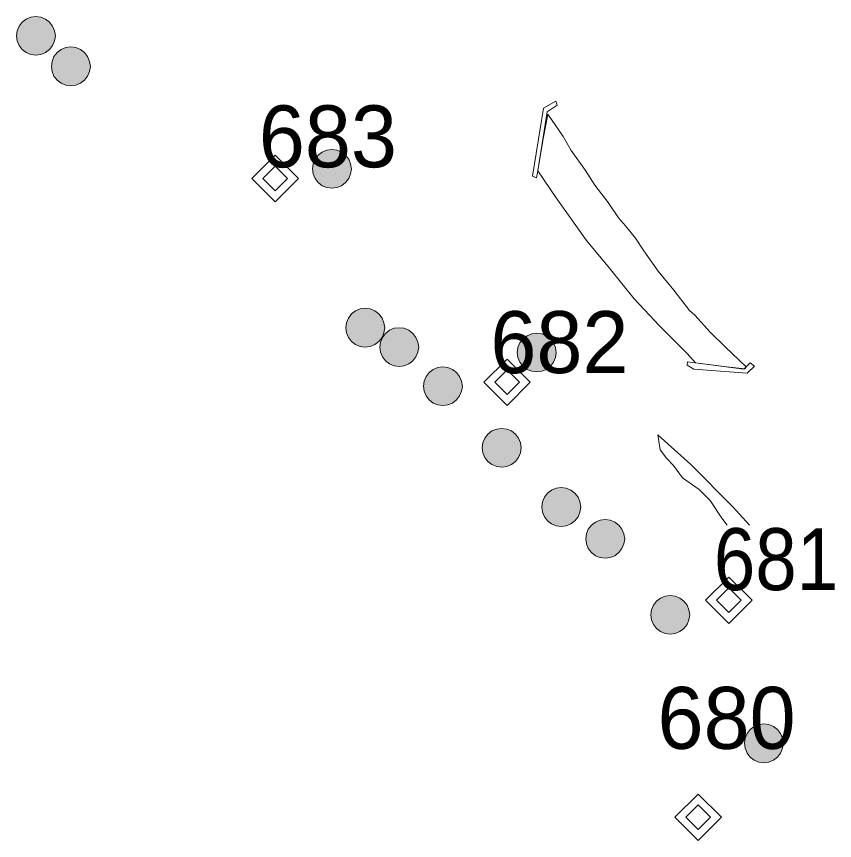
# Model space of a CAD drawing. Extents: x 3461750 to 3585707, y 5917729 to 5985917.
# Drawn here: x 3520979 to 3523622, y 5966054 to 5968716 of the extents above; entities that cross this region are included whole.
import ezdxf

# ---------------------------------------------------------------- set-up
doc = ezdxf.new("R2010")
doc.units = 0
doc.header["$LTSCALE"] = 80
for name, color, linetype, lineweight in [('13', 7, 'Continuous', 13), ('15', 7, 'Continuous', 13), ('2', 7, 'Continuous', 13), ('3', 7, 'Continuous', 13), ('6', 7, 'Continuous', 13), ('7', 7, 'Continuous', 13)]:
    doc.layers.add(name, color=color, linetype=linetype, lineweight=lineweight)

msp = doc.modelspace()

# ---------------------------------------------------------------- hatches: boundary and pattern name
at = {"layer": '3'}
for points in [[(3521105.17, 5968653.09), (3521102.24, 5968669.71), (3521095.99, 5968684.8), (3521086.04, 5968697.76), (3521073.08, 5968707.71), (3521057.99, 5968713.96), (3521041.8, 5968716.09), (3521025.6, 5968713.96), (3521010.51, 5968707.71), (3520997.55, 5968697.76), (3520987.61, 5968684.8), (3520981.35, 5968669.71), (3520979.22, 5968653.52), (3520981.35, 5968637.32), (3520987.61, 5968622.23), (3520997.55, 5968609.27), (3521010.51, 5968599.32), (3521025.6, 5968593.07), (3521041.8, 5968590.94), (3521057.99, 5968593.07), (3521073.08, 5968599.32), (3521086.04, 5968609.27), (3521095.99, 5968622.23), (3521102.24, 5968637.32)], [(3521217.82, 5968554.55), (3521214.89, 5968571.18), (3521208.63, 5968586.27), (3521198.69, 5968599.23), (3521185.73, 5968609.17), (3521170.64, 5968615.42), (3521154.44, 5968617.56), (3521138.25, 5968615.42), (3521123.16, 5968609.17), (3521110.2, 5968599.23), (3521100.25, 5968586.27), (3521094, 5968571.18), (3521091.87, 5968554.98), (3521094, 5968538.78), (3521100.25, 5968523.69), (3521110.2, 5968510.73), (3521123.16, 5968500.79), (3521138.25, 5968494.54), (3521154.44, 5968492.4), (3521170.64, 5968494.54), (3521185.73, 5968500.79), (3521198.69, 5968510.73), (3521208.63, 5968523.69), (3521214.89, 5968538.78)], [(3522061.66, 5968223.2), (3522058.73, 5968239.83), (3522052.48, 5968254.92), (3522042.54, 5968267.88), (3522029.58, 5968277.82), (3522014.49, 5968284.08), (3521998.29, 5968286.21), (3521982.1, 5968284.08), (3521967, 5968277.82), (3521954.04, 5968267.88), (3521944.1, 5968254.92), (3521937.85, 5968239.83), (3521935.72, 5968223.63), (3521937.85, 5968207.44), (3521944.1, 5968192.35), (3521954.04, 5968179.39), (3521967, 5968169.44), (3521982.1, 5968163.19), (3521998.29, 5968161.06), (3522014.49, 5968163.19), (3522029.58, 5968169.44), (3522042.54, 5968179.39), (3522052.48, 5968192.35), (3522058.73, 5968207.44)], [(3522169.23, 5967710.22), (3522166.3, 5967726.84), (3522160.05, 5967741.93), (3522150.11, 5967754.89), (3522137.15, 5967764.84), (3522122.05, 5967771.09), (3522105.86, 5967773.22), (3522089.66, 5967771.09), (3522074.57, 5967764.84), (3522061.61, 5967754.89), (3522051.67, 5967741.93), (3522045.42, 5967726.84), (3522043.28, 5967710.64), (3522045.42, 5967694.45), (3522051.67, 5967679.36), (3522061.61, 5967666.4), (3522074.57, 5967656.45), (3522089.66, 5967650.2), (3522105.86, 5967648.07), (3522122.05, 5967650.2), (3522137.15, 5967656.45), (3522150.11, 5967666.4), (3522160.05, 5967679.36), (3522166.3, 5967694.45)], [(3522279, 5967647.72), (3522276.07, 5967664.34), (3522269.82, 5967679.43), (3522259.87, 5967692.39), (3522246.91, 5967702.34), (3522231.82, 5967708.59), (3522215.62, 5967710.72), (3522199.43, 5967708.59), (3522184.34, 5967702.34), (3522171.38, 5967692.39), (3522161.43, 5967679.43), (3522155.18, 5967664.34), (3522153.05, 5967648.14), (3522155.18, 5967631.95), (3522161.43, 5967616.86), (3522171.38, 5967603.9), (3522184.34, 5967593.95), (3522199.43, 5967587.7), (3522215.62, 5967585.57), (3522231.82, 5967587.7), (3522246.91, 5967593.95), (3522259.87, 5967603.9), (3522269.82, 5967616.86), (3522276.07, 5967631.95)], [(3522723.14, 5967629.84), (3522720.21, 5967646.47), (3522713.96, 5967661.56), (3522704.01, 5967674.52), (3522691.05, 5967684.46), (3522675.96, 5967690.72), (3522659.77, 5967692.85), (3522643.57, 5967690.72), (3522628.48, 5967684.46), (3522615.52, 5967674.52), (3522605.57, 5967661.56), (3522599.32, 5967646.47), (3522597.19, 5967630.27), (3522599.32, 5967614.08), (3522605.57, 5967598.99), (3522615.52, 5967586.03), (3522628.48, 5967576.08), (3522643.57, 5967569.83), (3522659.77, 5967567.7), (3522675.96, 5967569.83), (3522691.05, 5967576.08), (3522704.01, 5967586.03), (3522713.96, 5967598.99), (3522720.21, 5967614.08)], [(3522419.92, 5967521.05), (3522416.99, 5967537.68), (3522410.73, 5967552.77), (3522400.79, 5967565.73), (3522387.83, 5967575.68), (3522372.74, 5967581.93), (3522356.54, 5967584.06), (3522340.35, 5967581.93), (3522325.26, 5967575.68), (3522312.3, 5967565.73), (3522302.35, 5967552.77), (3522296.1, 5967537.68), (3522293.97, 5967521.48), (3522296.1, 5967505.29), (3522302.35, 5967490.2), (3522312.3, 5967477.24), (3522325.26, 5967467.29), (3522340.35, 5967461.04), (3522356.54, 5967458.91), (3522372.74, 5967461.04), (3522387.83, 5967467.29), (3522400.79, 5967477.24), (3522410.73, 5967490.2), (3522416.99, 5967505.29)], [(3522610, 5967322.42), (3522607.07, 5967339.05), (3522600.82, 5967354.14), (3522590.88, 5967367.1), (3522577.92, 5967377.04), (3522562.83, 5967383.29), (3522546.63, 5967385.43), (3522530.44, 5967383.29), (3522515.34, 5967377.04), (3522502.38, 5967367.1), (3522492.44, 5967354.14), (3522486.19, 5967339.05), (3522484.06, 5967322.85), (3522486.19, 5967306.66), (3522492.44, 5967291.56), (3522502.38, 5967278.6), (3522515.34, 5967268.66), (3522530.44, 5967262.41), (3522546.63, 5967260.28), (3522562.83, 5967262.41), (3522577.92, 5967268.66), (3522590.88, 5967278.6), (3522600.82, 5967291.56), (3522607.07, 5967306.66)], [(3522802.39, 5967130.92), (3522799.46, 5967147.54), (3522793.21, 5967162.64), (3522783.26, 5967175.6), (3522770.3, 5967185.54), (3522755.21, 5967191.79), (3522739.01, 5967193.92), (3522722.82, 5967191.79), (3522707.73, 5967185.54), (3522694.77, 5967175.6), (3522684.82, 5967162.64), (3522678.57, 5967147.54), (3522676.44, 5967131.35), (3522678.57, 5967115.15), (3522684.82, 5967100.06), (3522694.77, 5967087.1), (3522707.73, 5967077.16), (3522722.82, 5967070.91), (3522739.01, 5967068.77), (3522755.21, 5967070.91), (3522770.3, 5967077.16), (3522783.26, 5967087.1), (3522793.21, 5967100.06), (3522799.46, 5967115.15)], [(3522943.94, 5967027.79), (3522941.01, 5967044.42), (3522934.76, 5967059.51), (3522924.81, 5967072.47), (3522911.85, 5967082.41), (3522896.76, 5967088.67), (3522880.57, 5967090.8), (3522864.37, 5967088.67), (3522849.28, 5967082.41), (3522836.32, 5967072.47), (3522826.37, 5967059.51), (3522820.12, 5967044.42), (3522817.99, 5967028.22), (3522820.12, 5967012.03), (3522826.37, 5966996.94), (3522836.32, 5966983.98), (3522849.28, 5966974.03), (3522864.37, 5966967.78), (3522880.57, 5966965.65), (3522896.76, 5966967.78), (3522911.85, 5966974.03), (3522924.81, 5966983.98), (3522934.76, 5966996.94), (3522941.01, 5967012.03)], [(3523154.49, 5966782.48), (3523151.56, 5966799.11), (3523145.3, 5966814.2), (3523135.36, 5966827.16), (3523122.4, 5966837.1), (3523107.31, 5966843.35), (3523091.11, 5966845.49), (3523074.92, 5966843.35), (3523059.83, 5966837.1), (3523046.87, 5966827.16), (3523036.92, 5966814.2), (3523030.67, 5966799.11), (3523028.54, 5966782.91), (3523030.67, 5966766.71), (3523036.92, 5966751.62), (3523046.87, 5966738.66), (3523059.83, 5966728.72), (3523074.92, 5966722.47), (3523091.11, 5966720.33), (3523107.31, 5966722.47), (3523122.4, 5966728.72), (3523135.36, 5966738.66), (3523145.3, 5966751.62), (3523151.56, 5966766.71)], [(3523457.02, 5966367.44), (3523454.09, 5966384.07), (3523447.84, 5966399.16), (3523437.9, 5966412.12), (3523424.94, 5966422.06), (3523409.85, 5966428.31), (3523393.65, 5966430.45), (3523377.46, 5966428.31), (3523362.36, 5966422.06), (3523349.4, 5966412.12), (3523339.46, 5966399.16), (3523333.21, 5966384.07), (3523331.08, 5966367.87), (3523333.21, 5966351.68), (3523339.46, 5966336.58), (3523349.4, 5966323.62), (3523362.36, 5966313.68), (3523377.46, 5966307.43), (3523393.65, 5966305.3), (3523409.85, 5966307.43), (3523424.94, 5966313.68), (3523437.9, 5966323.62), (3523447.84, 5966336.58), (3523454.09, 5966351.68)]]:
    msp.add_hatch(color=256, dxfattribs=at).paths.add_polyline_path(points)

# ---------------------------------------------------------------- linework, layer by layer
at = {"layer": '13'}
for points in [[(3523181.53, 5966204.01), (3523106.44, 5966128.92), (3523181.53, 5966053.83), (3523256.62, 5966128.92)], [(3523181.53, 5966168.61), (3523141.83, 5966128.92), (3523181.53, 5966089.23), (3523221.22, 5966128.92)]]:
    msp.add_lwpolyline(points, close=True, dxfattribs=at)
at = {"layer": '15'}
for points in [[(3521814.78, 5968267.78), (3521739.69, 5968192.69), (3521814.78, 5968117.6), (3521889.87, 5968192.69)], [(3521814.78, 5968232.38), (3521775.09, 5968192.69), (3521814.78, 5968153), (3521854.47, 5968192.69)], [(3522564, 5967609.38), (3522488.91, 5967534.29), (3522564, 5967459.2), (3522639.09, 5967534.29)], [(3522564, 5967573.98), (3522524.31, 5967534.29), (3522564, 5967494.6), (3522603.69, 5967534.29)], [(3523280.45, 5966905.08), (3523205.36, 5966829.99), (3523280.45, 5966754.9), (3523355.54, 5966829.99)], [(3523280.45, 5966869.69), (3523240.76, 5966829.99), (3523280.45, 5966790.3), (3523320.15, 5966829.99)]]:
    msp.add_lwpolyline(points, close=True, dxfattribs=at)
at = {"layer": '2'}
for points in [[(3523347.05, 5967072.8), (3523293.55, 5967131.45), (3523157.23, 5967268.26), (3523051.27, 5967364.65)], [(3523275.02, 5967072.8), (3523258.06, 5967095.61), (3523219.92, 5967152.44), (3523184.42, 5967187.7), (3523130.52, 5967225.88), (3523101.32, 5967265.33), (3523079.59, 5967289.36), (3523058.74, 5967315.82), (3523051.27, 5967364.65)]]:
    msp.add_lwpolyline(points, dxfattribs=at)
at = {"layer": '3'}
for points in [[(3521105.17, 5968653.09), (3521102.24, 5968669.71), (3521095.99, 5968684.8), (3521086.04, 5968697.76), (3521073.08, 5968707.71), (3521057.99, 5968713.96), (3521041.8, 5968716.09), (3521025.6, 5968713.96), (3521010.51, 5968707.71), (3520997.55, 5968697.76), (3520987.61, 5968684.8), (3520981.35, 5968669.71), (3520979.22, 5968653.52), (3520981.35, 5968637.32), (3520987.61, 5968622.23), (3520997.55, 5968609.27), (3521010.51, 5968599.32), (3521025.6, 5968593.07), (3521041.8, 5968590.94), (3521057.99, 5968593.07), (3521073.08, 5968599.32), (3521086.04, 5968609.27), (3521095.99, 5968622.23), (3521102.24, 5968637.32)], [(3521217.82, 5968554.55), (3521214.89, 5968571.18), (3521208.63, 5968586.27), (3521198.69, 5968599.23), (3521185.73, 5968609.17), (3521170.64, 5968615.42), (3521154.44, 5968617.56), (3521138.25, 5968615.42), (3521123.16, 5968609.17), (3521110.2, 5968599.23), (3521100.25, 5968586.27), (3521094, 5968571.18), (3521091.87, 5968554.98), (3521094, 5968538.78), (3521100.25, 5968523.69), (3521110.2, 5968510.73), (3521123.16, 5968500.79), (3521138.25, 5968494.54), (3521154.44, 5968492.4), (3521170.64, 5968494.54), (3521185.73, 5968500.79), (3521198.69, 5968510.73), (3521208.63, 5968523.69), (3521214.89, 5968538.78)], [(3522061.66, 5968223.2), (3522058.73, 5968239.83), (3522052.48, 5968254.92), (3522042.54, 5968267.88), (3522029.58, 5968277.82), (3522014.49, 5968284.08), (3521998.29, 5968286.21), (3521982.1, 5968284.08), (3521967, 5968277.82), (3521954.04, 5968267.88), (3521944.1, 5968254.92), (3521937.85, 5968239.83), (3521935.72, 5968223.63), (3521937.85, 5968207.44), (3521944.1, 5968192.35), (3521954.04, 5968179.39), (3521967, 5968169.44), (3521982.1, 5968163.19), (3521998.29, 5968161.06), (3522014.49, 5968163.19), (3522029.58, 5968169.44), (3522042.54, 5968179.39), (3522052.48, 5968192.35), (3522058.73, 5968207.44)], [(3522169.23, 5967710.22), (3522166.3, 5967726.84), (3522160.05, 5967741.93), (3522150.11, 5967754.89), (3522137.15, 5967764.84), (3522122.05, 5967771.09), (3522105.86, 5967773.22), (3522089.66, 5967771.09), (3522074.57, 5967764.84), (3522061.61, 5967754.89), (3522051.67, 5967741.93), (3522045.42, 5967726.84), (3522043.28, 5967710.64), (3522045.42, 5967694.45), (3522051.67, 5967679.36), (3522061.61, 5967666.4), (3522074.57, 5967656.45), (3522089.66, 5967650.2), (3522105.86, 5967648.07), (3522122.05, 5967650.2), (3522137.15, 5967656.45), (3522150.11, 5967666.4), (3522160.05, 5967679.36), (3522166.3, 5967694.45)], [(3522279, 5967647.72), (3522276.07, 5967664.34), (3522269.82, 5967679.43), (3522259.87, 5967692.39), (3522246.91, 5967702.34), (3522231.82, 5967708.59), (3522215.62, 5967710.72), (3522199.43, 5967708.59), (3522184.34, 5967702.34), (3522171.38, 5967692.39), (3522161.43, 5967679.43), (3522155.18, 5967664.34), (3522153.05, 5967648.14), (3522155.18, 5967631.95), (3522161.43, 5967616.86), (3522171.38, 5967603.9), (3522184.34, 5967593.95), (3522199.43, 5967587.7), (3522215.62, 5967585.57), (3522231.82, 5967587.7), (3522246.91, 5967593.95), (3522259.87, 5967603.9), (3522269.82, 5967616.86), (3522276.07, 5967631.95)], [(3522723.14, 5967629.84), (3522720.21, 5967646.47), (3522713.96, 5967661.56), (3522704.01, 5967674.52), (3522691.05, 5967684.46), (3522675.96, 5967690.72), (3522659.77, 5967692.85), (3522643.57, 5967690.72), (3522628.48, 5967684.46), (3522615.52, 5967674.52), (3522605.57, 5967661.56), (3522599.32, 5967646.47), (3522597.19, 5967630.27), (3522599.32, 5967614.08), (3522605.57, 5967598.99), (3522615.52, 5967586.03), (3522628.48, 5967576.08), (3522643.57, 5967569.83), (3522659.77, 5967567.7), (3522675.96, 5967569.83), (3522691.05, 5967576.08), (3522704.01, 5967586.03), (3522713.96, 5967598.99), (3522720.21, 5967614.08)], [(3522419.92, 5967521.05), (3522416.99, 5967537.68), (3522410.73, 5967552.77), (3522400.79, 5967565.73), (3522387.83, 5967575.68), (3522372.74, 5967581.93), (3522356.54, 5967584.06), (3522340.35, 5967581.93), (3522325.26, 5967575.68), (3522312.3, 5967565.73), (3522302.35, 5967552.77), (3522296.1, 5967537.68), (3522293.97, 5967521.48), (3522296.1, 5967505.29), (3522302.35, 5967490.2), (3522312.3, 5967477.24), (3522325.26, 5967467.29), (3522340.35, 5967461.04), (3522356.54, 5967458.91), (3522372.74, 5967461.04), (3522387.83, 5967467.29), (3522400.79, 5967477.24), (3522410.73, 5967490.2), (3522416.99, 5967505.29)], [(3522610, 5967322.42), (3522607.07, 5967339.05), (3522600.82, 5967354.14), (3522590.88, 5967367.1), (3522577.92, 5967377.04), (3522562.83, 5967383.29), (3522546.63, 5967385.43), (3522530.44, 5967383.29), (3522515.34, 5967377.04), (3522502.38, 5967367.1), (3522492.44, 5967354.14), (3522486.19, 5967339.05), (3522484.06, 5967322.85), (3522486.19, 5967306.66), (3522492.44, 5967291.56), (3522502.38, 5967278.6), (3522515.34, 5967268.66), (3522530.44, 5967262.41), (3522546.63, 5967260.28), (3522562.83, 5967262.41), (3522577.92, 5967268.66), (3522590.88, 5967278.6), (3522600.82, 5967291.56), (3522607.07, 5967306.66)], [(3522802.39, 5967130.92), (3522799.46, 5967147.54), (3522793.21, 5967162.64), (3522783.26, 5967175.6), (3522770.3, 5967185.54), (3522755.21, 5967191.79), (3522739.01, 5967193.92), (3522722.82, 5967191.79), (3522707.73, 5967185.54), (3522694.77, 5967175.6), (3522684.82, 5967162.64), (3522678.57, 5967147.54), (3522676.44, 5967131.35), (3522678.57, 5967115.15), (3522684.82, 5967100.06), (3522694.77, 5967087.1), (3522707.73, 5967077.16), (3522722.82, 5967070.91), (3522739.01, 5967068.77), (3522755.21, 5967070.91), (3522770.3, 5967077.16), (3522783.26, 5967087.1), (3522793.21, 5967100.06), (3522799.46, 5967115.15)], [(3522943.94, 5967027.79), (3522941.01, 5967044.42), (3522934.76, 5967059.51), (3522924.81, 5967072.47), (3522911.85, 5967082.41), (3522896.76, 5967088.67), (3522880.57, 5967090.8), (3522864.37, 5967088.67), (3522849.28, 5967082.41), (3522836.32, 5967072.47), (3522826.37, 5967059.51), (3522820.12, 5967044.42), (3522817.99, 5967028.22), (3522820.12, 5967012.03), (3522826.37, 5966996.94), (3522836.32, 5966983.98), (3522849.28, 5966974.03), (3522864.37, 5966967.78), (3522880.57, 5966965.65), (3522896.76, 5966967.78), (3522911.85, 5966974.03), (3522924.81, 5966983.98), (3522934.76, 5966996.94), (3522941.01, 5967012.03)], [(3523154.49, 5966782.48), (3523151.56, 5966799.11), (3523145.3, 5966814.2), (3523135.36, 5966827.16), (3523122.4, 5966837.1), (3523107.31, 5966843.35), (3523091.11, 5966845.49), (3523074.92, 5966843.35), (3523059.83, 5966837.1), (3523046.87, 5966827.16), (3523036.92, 5966814.2), (3523030.67, 5966799.11), (3523028.54, 5966782.91), (3523030.67, 5966766.71), (3523036.92, 5966751.62), (3523046.87, 5966738.66), (3523059.83, 5966728.72), (3523074.92, 5966722.47), (3523091.11, 5966720.33), (3523107.31, 5966722.47), (3523122.4, 5966728.72), (3523135.36, 5966738.66), (3523145.3, 5966751.62), (3523151.56, 5966766.71)], [(3523457.02, 5966367.44), (3523454.09, 5966384.07), (3523447.84, 5966399.16), (3523437.9, 5966412.12), (3523424.94, 5966422.06), (3523409.85, 5966428.31), (3523393.65, 5966430.45), (3523377.46, 5966428.31), (3523362.36, 5966422.06), (3523349.4, 5966412.12), (3523339.46, 5966399.16), (3523333.21, 5966384.07), (3523331.08, 5966367.87), (3523333.21, 5966351.68), (3523339.46, 5966336.58), (3523349.4, 5966323.62), (3523362.36, 5966313.68), (3523377.46, 5966307.43), (3523393.65, 5966305.3), (3523409.85, 5966307.43), (3523424.94, 5966313.68), (3523437.9, 5966323.62), (3523447.84, 5966336.58), (3523454.09, 5966351.68)]]:
    msp.add_lwpolyline(points, close=True, dxfattribs=at)
at = {"layer": '6'}
for points in [[(3522663.09, 5968217.7), (3522680.27, 5968320.62), (3522695.45, 5968400.05), (3522745.48, 5968327.85), (3522770.72, 5968282.57), (3522817.9, 5968218.02), (3522847.18, 5968170.64), (3522890.6, 5968114.69), (3522924.48, 5968065.57), (3522946.87, 5968039.81), (3522978.86, 5967999.8), (3523005.46, 5967958.78), (3523051.68, 5967893.53), (3523102.78, 5967832.28), (3523153.06, 5967766.23), (3523170.42, 5967750.75), (3523220.14, 5967696.02), (3523269.94, 5967647.22), (3523336.38, 5967583.88), (3523332.2, 5967577.84), (3523273.93, 5967584.18), (3523172.97, 5967597.21)], [(3522663.09, 5968217.7), (3522722.66, 5968129.95), (3522820.79, 5967992.84), (3522894.44, 5967903.22), (3522974.98, 5967803.68), (3523056.07, 5967716.74), (3523145.82, 5967627.07), (3523172.97, 5967597.21)]]:
    msp.add_lwpolyline(points, dxfattribs=at)
at = {"layer": '7'}
for p, q in [((3522663.09, 5968217.7), (3522659.54, 5968195.32)), ((3523146.87, 5967600.57), (3523172.97, 5967597.21))]:
    msp.add_line(p, q, dxfattribs=at)
for points in [[(3522659.54, 5968195.32), (3522646.64, 5968199.99), (3522681.67, 5968420.3), (3522721.16, 5968442.24), (3522726.15, 5968429.74), (3522693.35, 5968408.43), (3522663.09, 5968217.7)], [(3522663.09, 5968217.7), (3522722.66, 5968129.95), (3522820.79, 5967992.84), (3522894.44, 5967903.22), (3522974.98, 5967803.68), (3523056.07, 5967716.74), (3523145.82, 5967627.07), (3523172.97, 5967597.21)], [(3523172.97, 5967597.21), (3523328.49, 5967577.16), (3523349.01, 5967597.37), (3523363.28, 5967586.2), (3523339.2, 5967563.46), (3523167.43, 5967576.52), (3523145.4, 5967589.86), (3523146.87, 5967600.57)]]:
    msp.add_lwpolyline(points, dxfattribs=at)

# ---------------------------------------------------------------- texts
at = {"layer": '13'}
msp.add_text('680', height=200, dxfattribs=at).set_placement((3523050, 5966350))
at = {"layer": '15'}
for s, p in [('683', (3521762.1, 5968228.8)), ('682', (3522510.1, 5967564))]:
    msp.add_text(s, height=200, dxfattribs=at).set_placement(p)
at = {"layer": '15', "width": 0.9}
msp.add_text('681', height=200, dxfattribs=at).set_placement((3523232, 5966862.8))

doc.saveas('drawing.dxf')
